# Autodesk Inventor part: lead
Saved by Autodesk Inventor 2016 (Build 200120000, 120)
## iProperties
Created: 2016-09
Part Number: lead
Material: Generic
Document SubType Name: Modeling
Designer: Administrator
Appearance: Generic
Author: Administrator
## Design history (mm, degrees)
feature "Body1"
feature "Body2"
feature "Body3"
feature "Body4"
feature "Body6"
feature "Body10"
feature "Body14"
feature "Body7"
feature "Body11"
feature "Body15"
feature "Body8"
feature "Body12"
feature "Body16"
feature "Body5"
feature "Body9"
feature "Body13"
body "Solid1"
body "Solid2"
body "Solid3"
body "Solid4"
body "Solid5"
body "Solid6"
body "Solid7"
body "Solid8"
body "Solid9"
body "Solid10"
body "Solid11"
body "Solid12"
body "Solid13"
body "Solid14"
body "Solid15"
body "Solid16"
